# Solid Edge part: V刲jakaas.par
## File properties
Author: Türk
Template: iso part.par
Last saved by: Türk
Revision: 14
Application: Solid Edge
Accuracy: 0,990
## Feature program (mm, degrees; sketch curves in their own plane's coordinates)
base feature "unnamed BaseFeature 1"
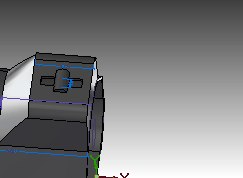
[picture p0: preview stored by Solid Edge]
